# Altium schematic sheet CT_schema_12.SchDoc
size 742 x 542 mm
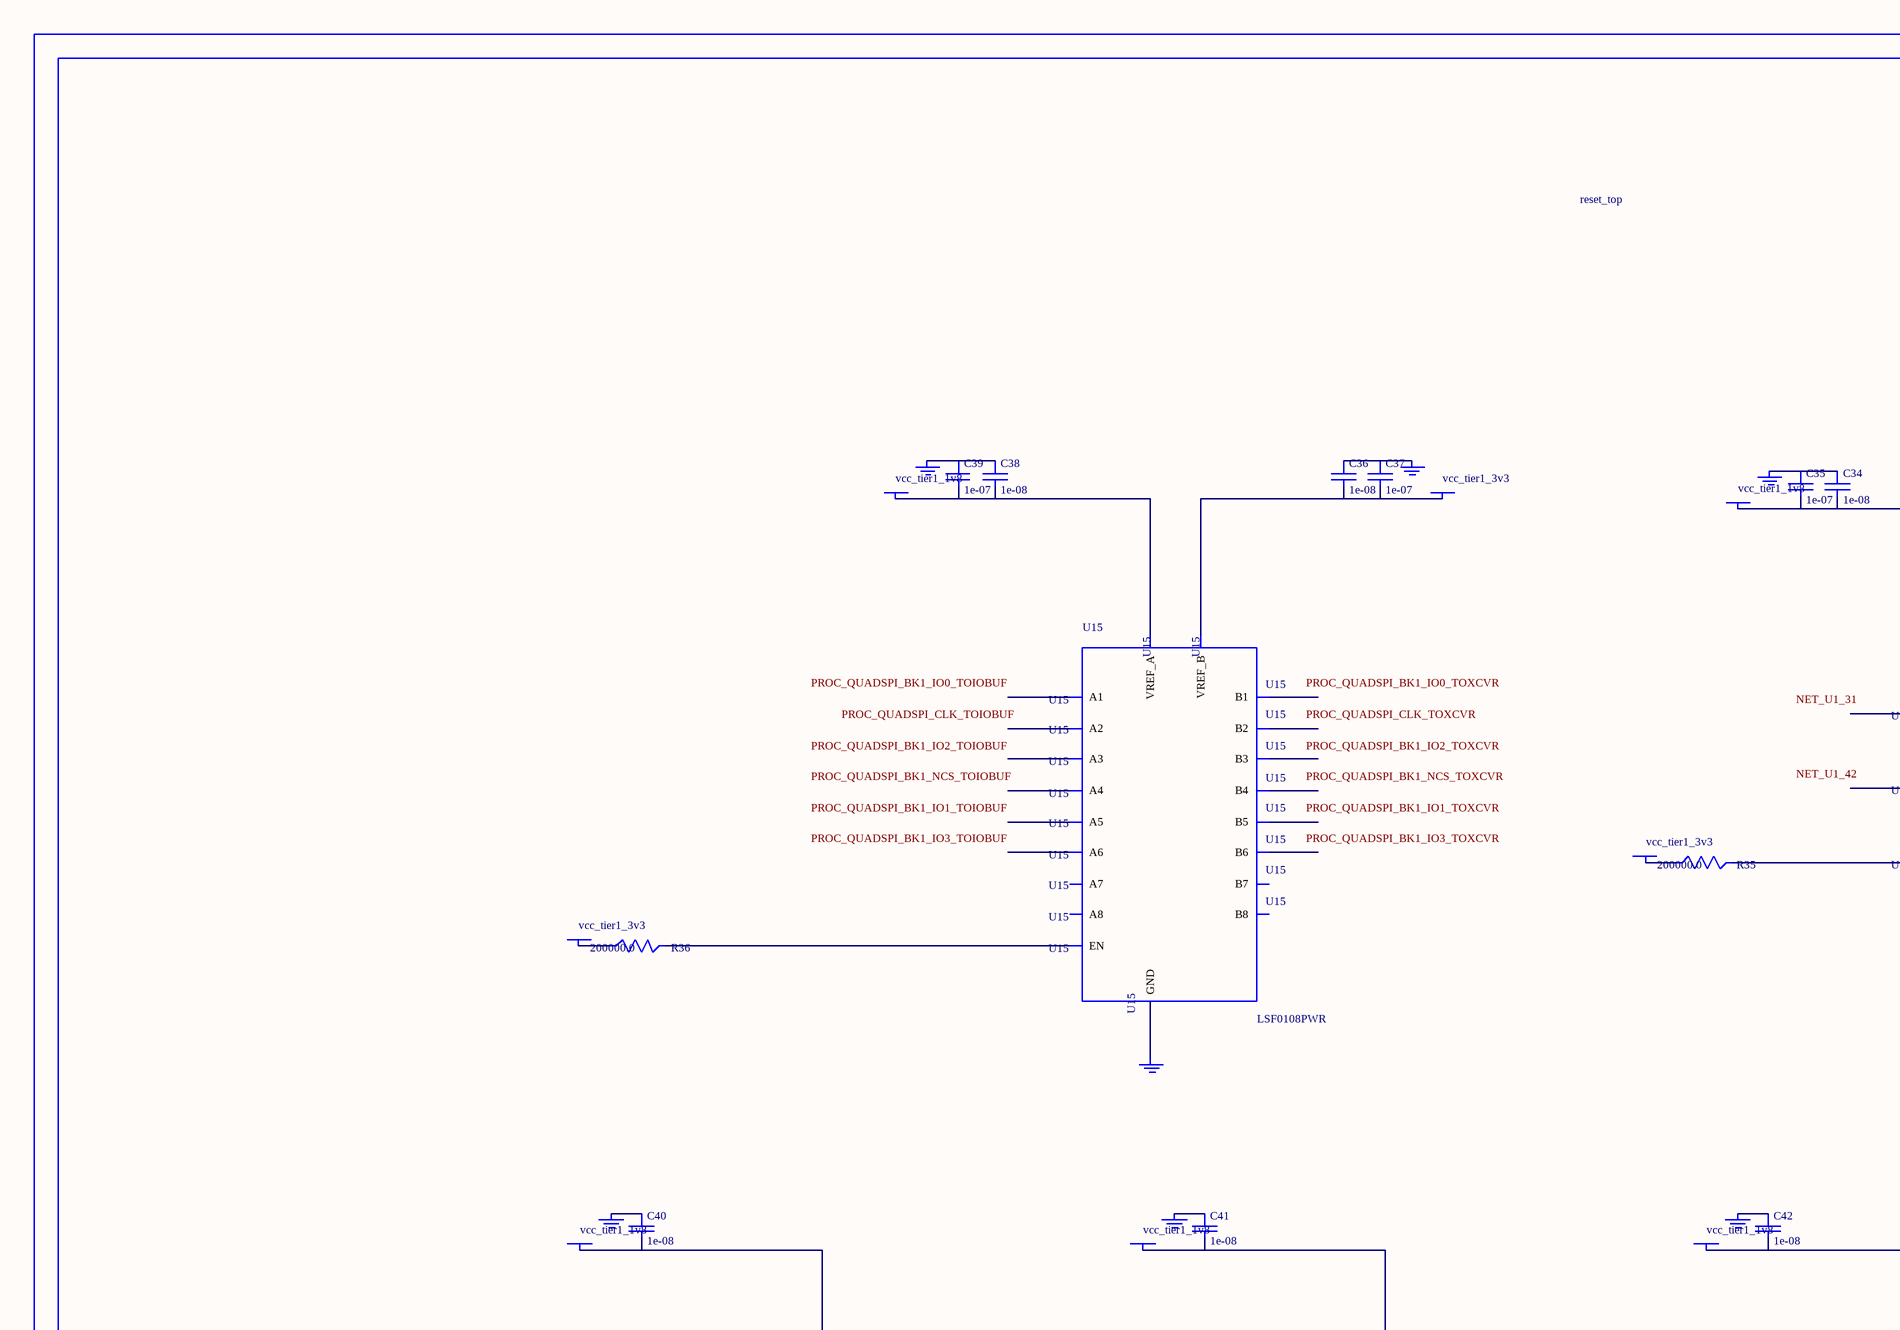
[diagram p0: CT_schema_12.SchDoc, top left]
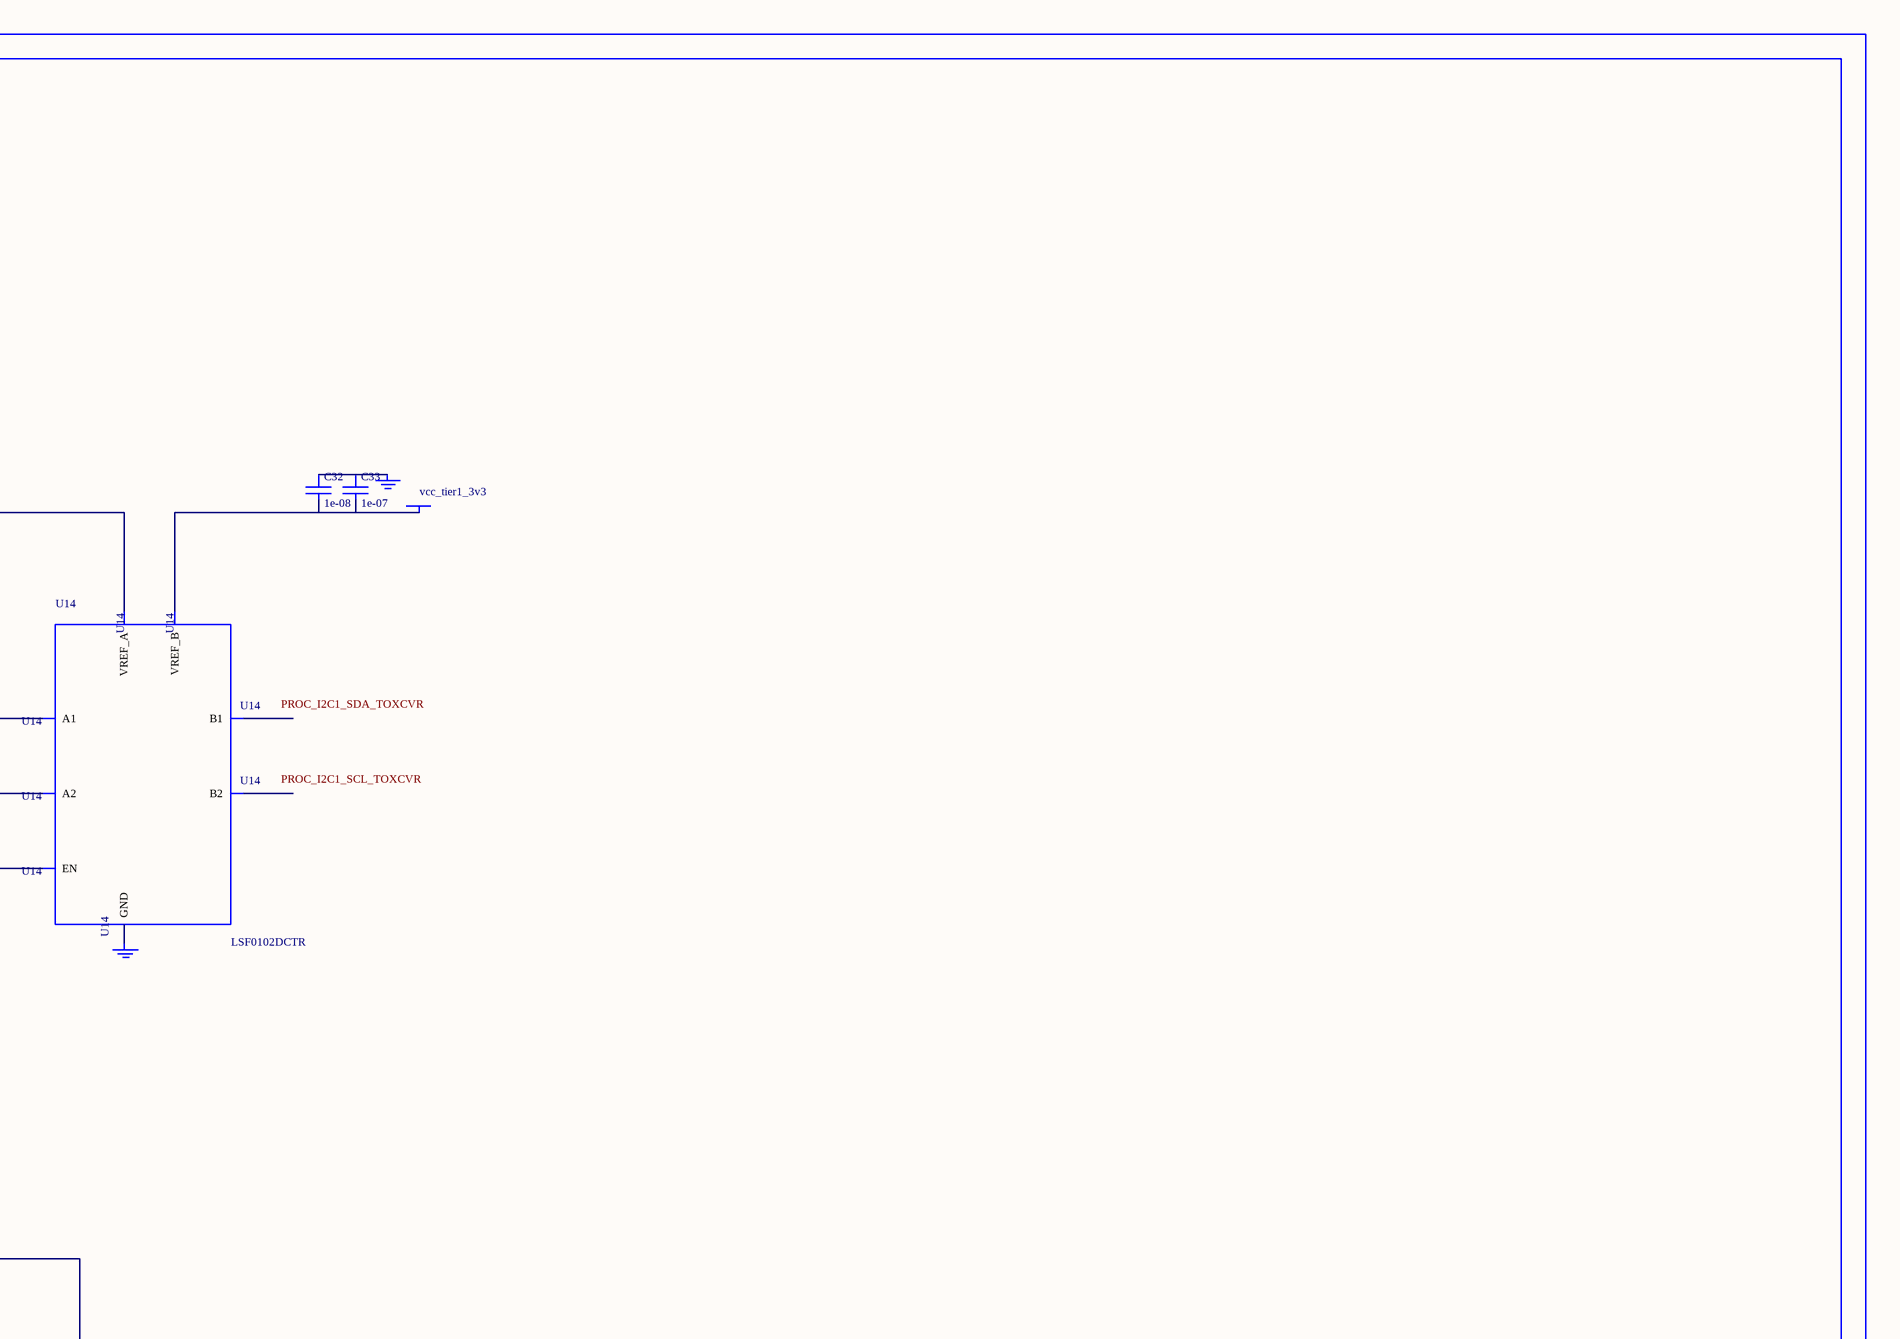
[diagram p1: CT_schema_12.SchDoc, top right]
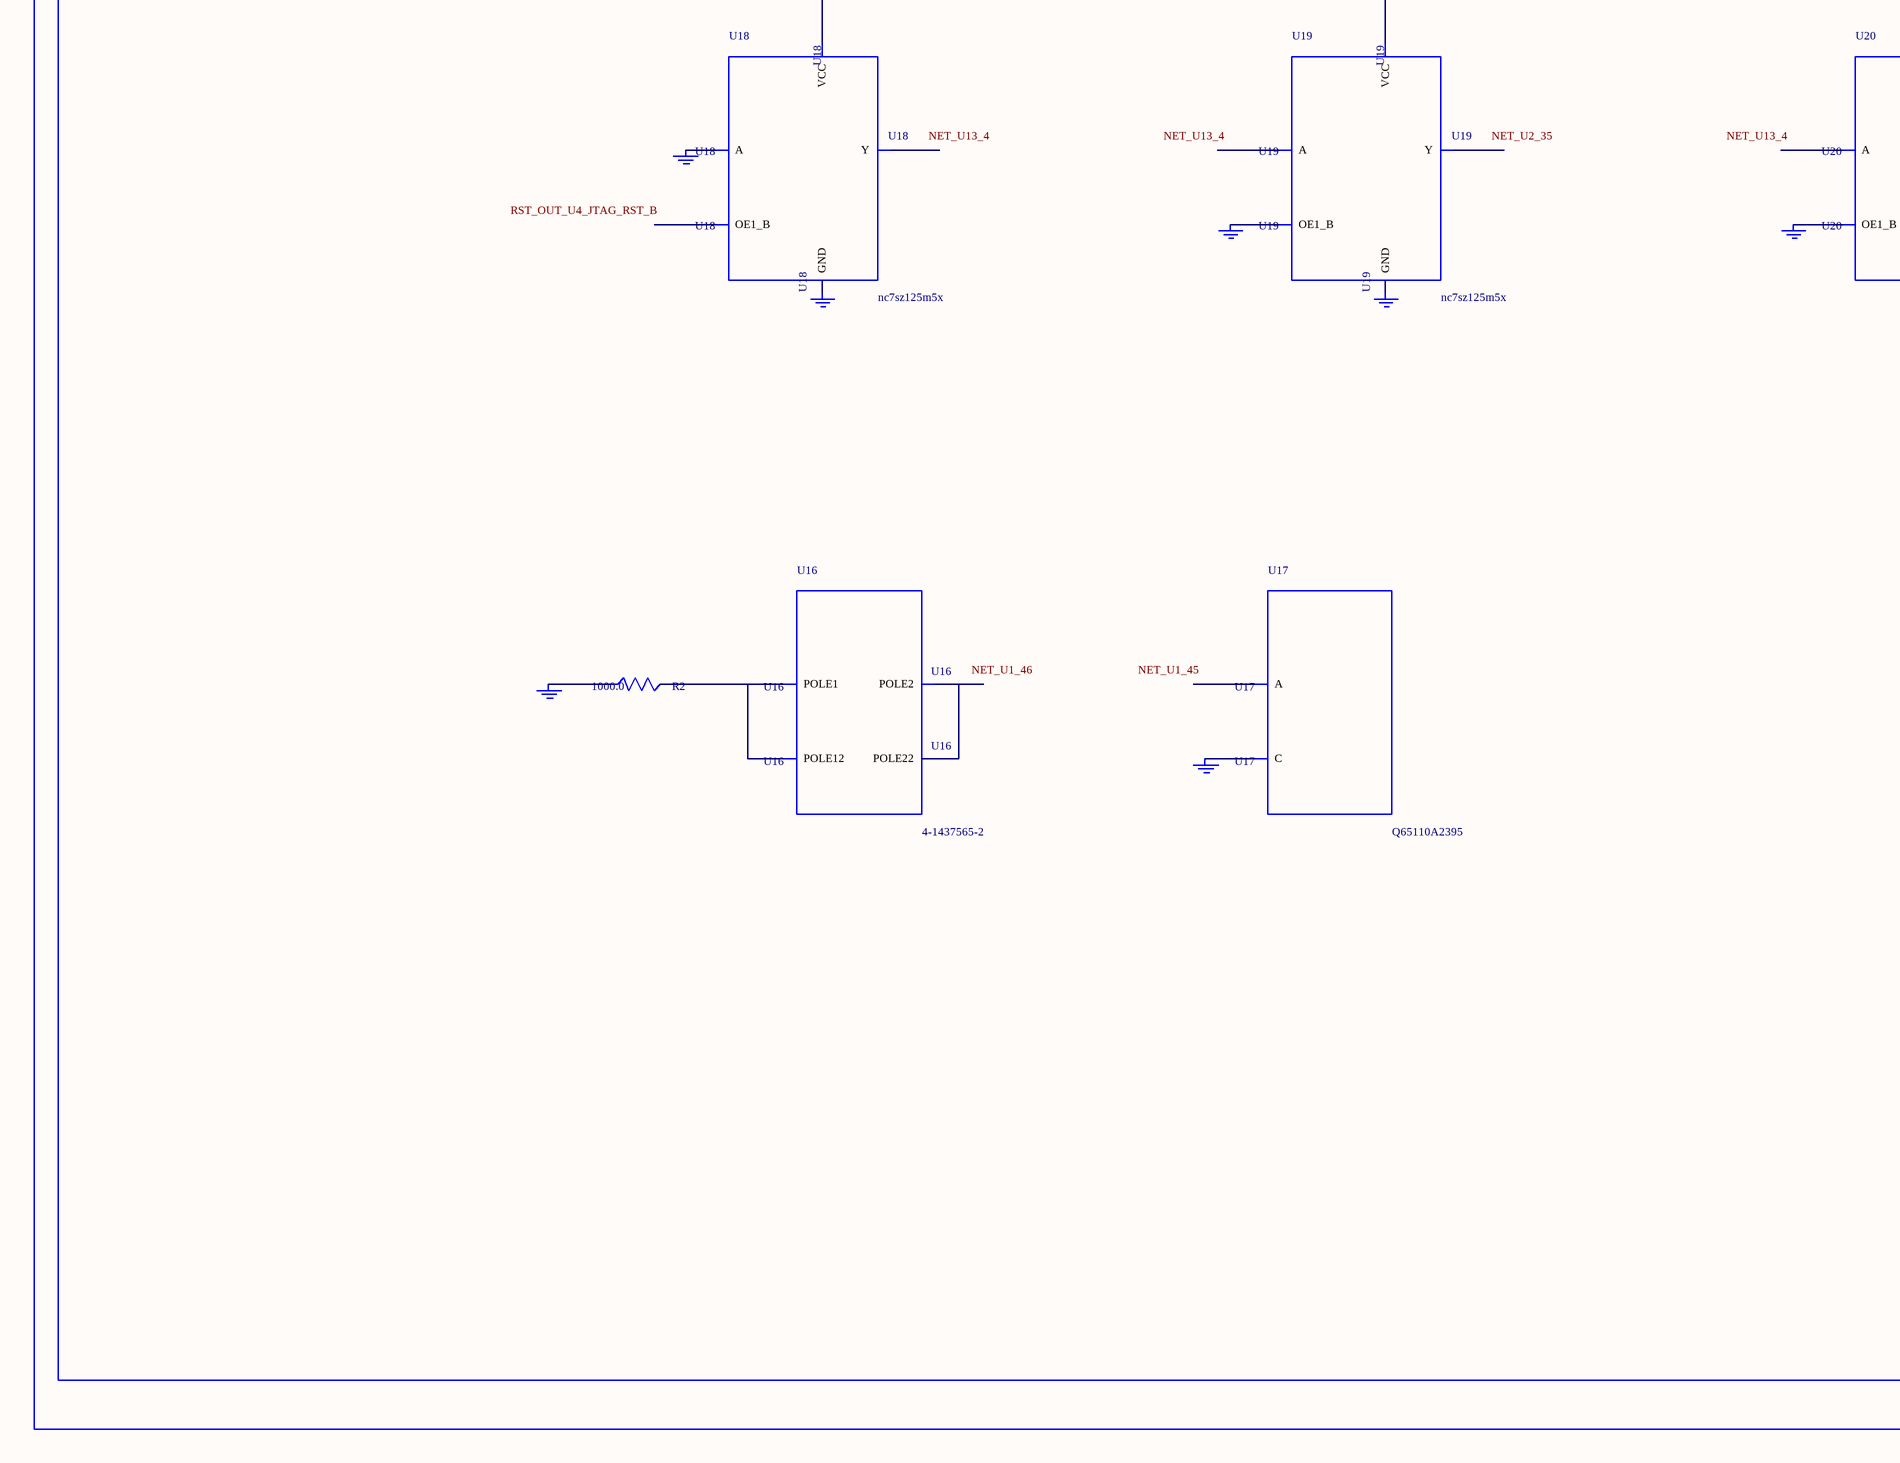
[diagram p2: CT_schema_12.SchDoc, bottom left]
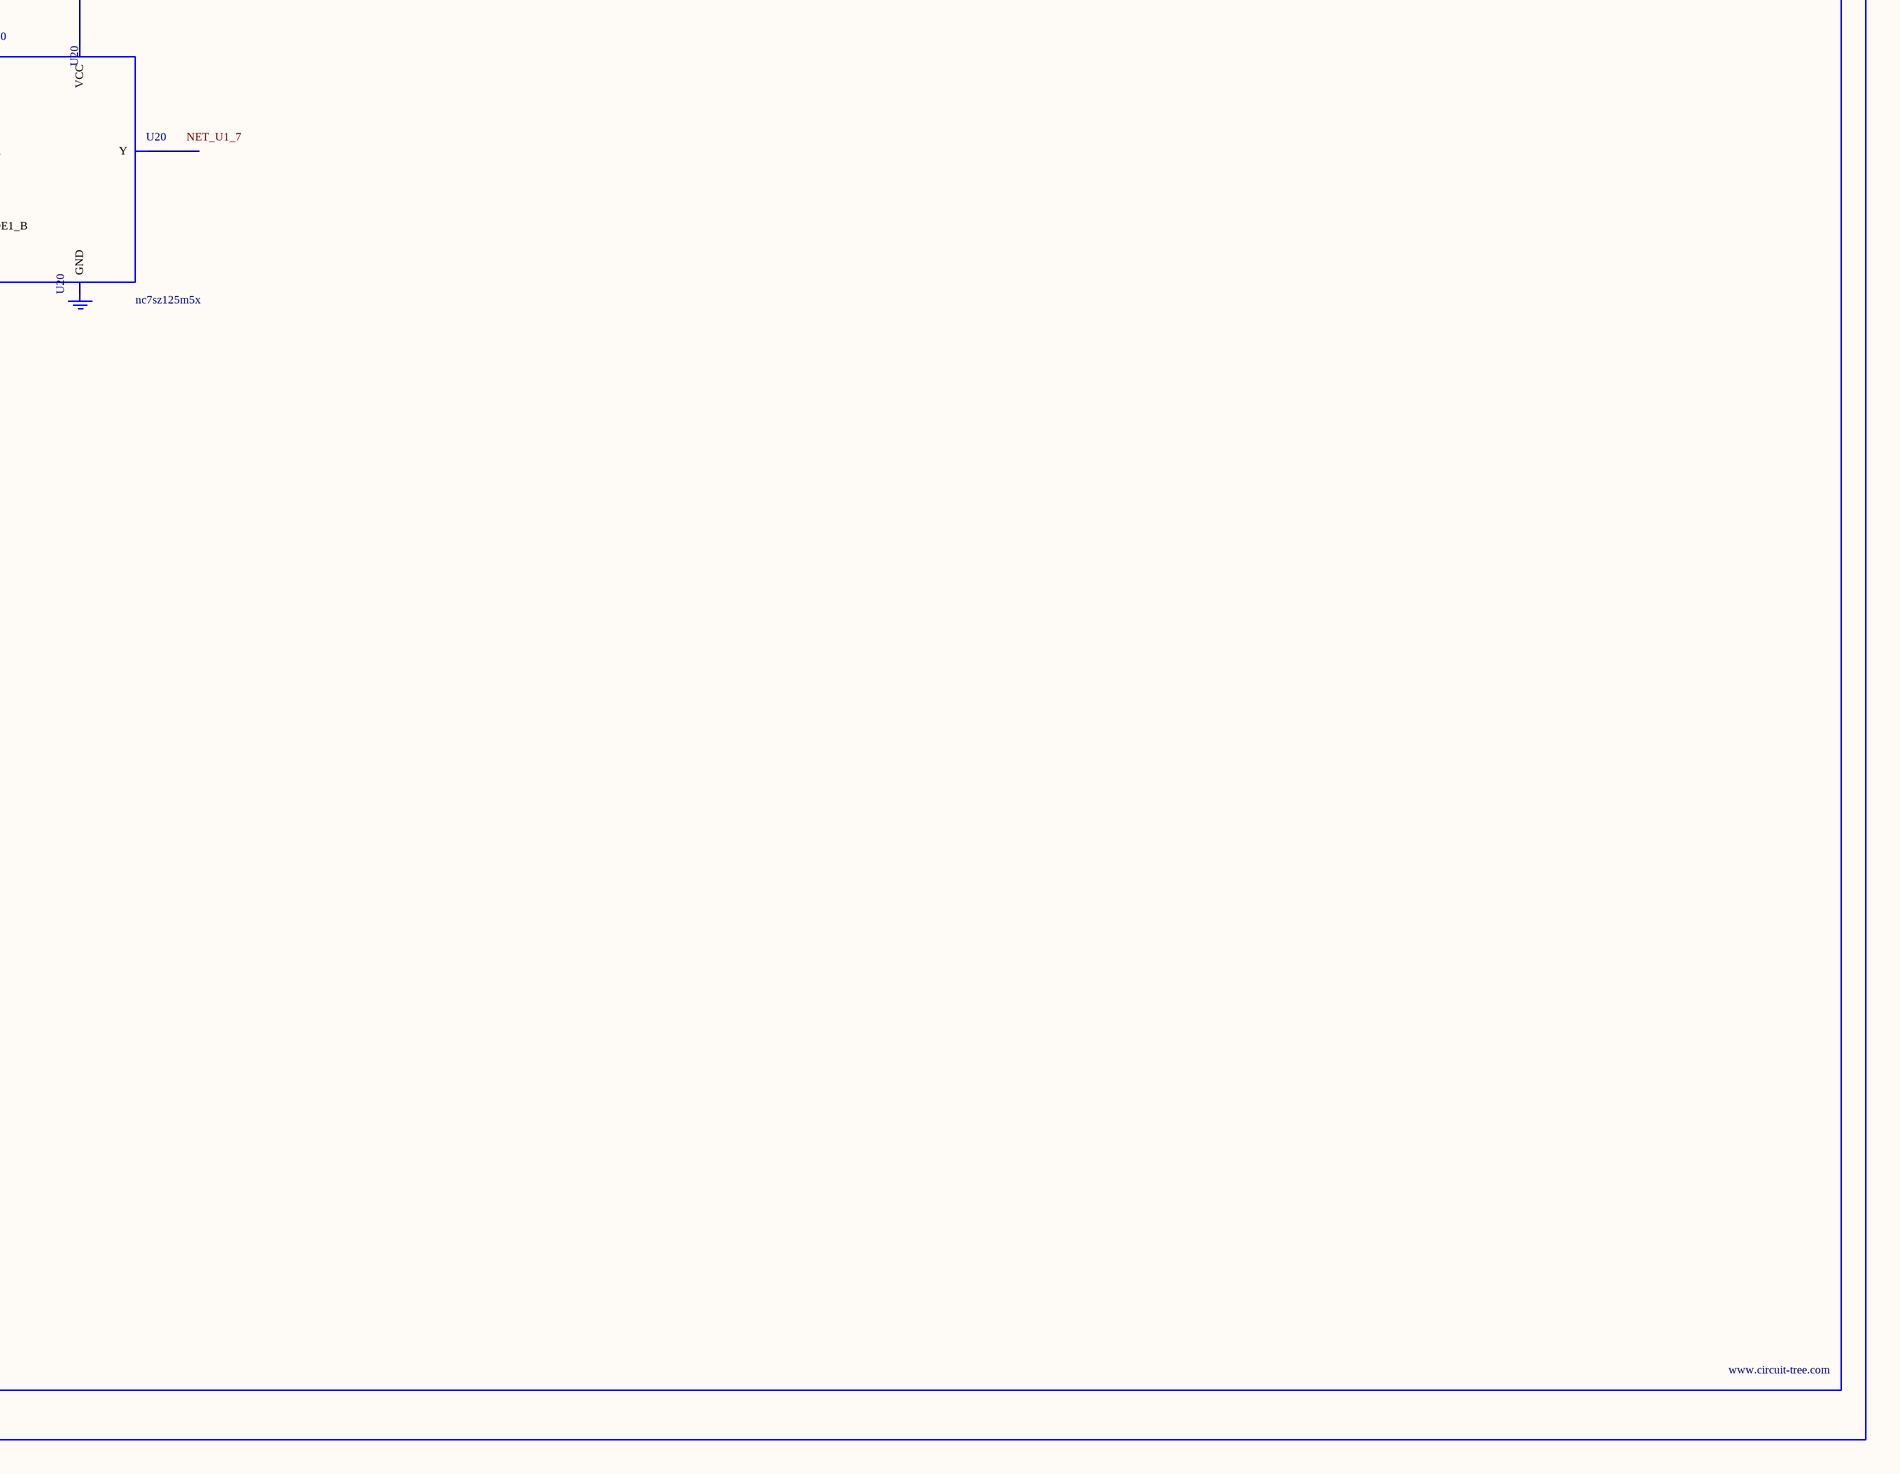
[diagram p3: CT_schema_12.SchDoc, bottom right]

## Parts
BORDER11  (no value)
C32  1e-08  [C0402]
C33  1e-07  [C0402]
C34  1e-08  [C0402]
C35  1e-07  [C0402]
C36  1e-08  [C0402]
C37  1e-07  [C0402]
C38  1e-08  [C0402]
C39  1e-07  [C0402]
C40  1e-08  [C0402]
C41  1e-08  [C0402]
C42  1e-08  [C0402]
GND_INSTANCE_11_0  (no value)
GND_INSTANCE_11_1  (no value)
GND_INSTANCE_11_2  (no value)
GND_INSTANCE_11_3  (no value)
GND_INSTANCE_11_4  (no value)
GND_INSTANCE_11_5  (no value)
GND_INSTANCE_11_6  (no value)
GND_INSTANCE_11_7  (no value)
GND_INSTANCE_11_8  (no value)
GND_INSTANCE_11_9  (no value)
GND_INSTANCE_11_10  (no value)
GND_INSTANCE_11_11  (no value)
GND_INSTANCE_11_12  (no value)
GND_INSTANCE_11_13  (no value)
GND_INSTANCE_11_14  (no value)
GND_INSTANCE_11_15  (no value)
GND_INSTANCE_11_16  (no value)
POWER_INSTANCE_11_0  vcc_tier1_1v8
POWER_INSTANCE_11_1  vcc_tier1_3v3
POWER_INSTANCE_11_2  vcc_tier1_3v3
POWER_INSTANCE_11_3  vcc_tier1_1v8
POWER_INSTANCE_11_4  vcc_tier1_3v3
POWER_INSTANCE_11_5  vcc_tier1_3v3
POWER_INSTANCE_11_6  vcc_tier1_1v8
POWER_INSTANCE_11_7  vcc_tier1_1v8
POWER_INSTANCE_11_8  vcc_tier1_1v8
R2  1000.0  [R0603]
R35  200000.0  [R0603]
R36  200000.0  [R0603]
U14  LSF0102DCTR  [DCU0008A_N]
U15  LSF0108PWR  [PW0020A]
U16  4-1437565-2  [SW_4-1437565-2]
U17  Q65110A2395  [LGM67K-G1J2-24-Z]
U18  nc7sz125m5x  [NC7SZ125M5X]
U19  nc7sz125m5x  [NC7SZ125M5X]
U20  nc7sz125m5x  [NC7SZ125M5X]

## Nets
NetC32_1: C32.1 C33.1 GND_INSTANCE_11_1.0(GND)
NetC32_2: C32.2 C33.2 POWER_INSTANCE_11_1.0(PWR) U14.7(VREF_B)
NetC34_1: C34.1 C35.1 GND_INSTANCE_11_0.0(GND)
NetC34_2: C34.2 C35.2 POWER_INSTANCE_11_0.0(PWR) U14.2(VREF_A)
NetC36_1: C36.1 C37.1 GND_INSTANCE_11_4.0(GND)
NetC36_2: C36.2 C37.2 POWER_INSTANCE_11_4.0(PWR) U15.19(VREF_B)
NetC38_1: C38.1 C39.1 GND_INSTANCE_11_3.0(GND)
NetC38_2: C38.2 C39.2 POWER_INSTANCE_11_3.0(PWR) U15.2(VREF_A)
NetC40_1: C40.1 GND_INSTANCE_11_8.0(GND)
NetC40_2: C40.2 POWER_INSTANCE_11_6.0(PWR) U18.5(VCC)
NetC41_1: C41.1 GND_INSTANCE_11_11.0(GND)
NetC41_2: C41.2 POWER_INSTANCE_11_7.0(PWR) U19.5(VCC)
NetC42_1: C42.1 GND_INSTANCE_11_14.0(GND)
NetC42_2: C42.2 POWER_INSTANCE_11_8.0(PWR) U20.5(VCC)
NetGND_INSTANCE_11_2_0: GND_INSTANCE_11_2.0(GND) U14.1(GND)
NetGND_INSTANCE_11_5_0: GND_INSTANCE_11_5.0(GND) U15.1(GND)
NetGND_INSTANCE_11_6_0: GND_INSTANCE_11_6.0(GND) R2.1
NetGND_INSTANCE_11_7_0: GND_INSTANCE_11_7.0(GND) U17.C
NetGND_INSTANCE_11_9_0: GND_INSTANCE_11_9.0(GND) U18.2(A)
NetGND_INSTANCE_11_10_0: GND_INSTANCE_11_10.0(GND) U18.3(GND)
NetGND_INSTANCE_11_12_0: GND_INSTANCE_11_12.0(GND) U19.1(OE1_B)
NetGND_INSTANCE_11_13_0: GND_INSTANCE_11_13.0(GND) U19.3(GND)
NetGND_INSTANCE_11_15_0: GND_INSTANCE_11_15.0(GND) U20.1(OE1_B)
NetGND_INSTANCE_11_16_0: GND_INSTANCE_11_16.0(GND) U20.3(GND)
NetPOWER_INSTANCE_11_2_0: POWER_INSTANCE_11_2.0(PWR) R35.1
NetPOWER_INSTANCE_11_5_0: POWER_INSTANCE_11_5.0(PWR) R36.1
NetR2_2: R2.2 U16.1(POLE1) U16.2(POLE12)
NetR35_2: R35.2 U14.8(EN)
NetR36_2: R36.2 U15.20(EN)
NetU16_3: U16.3(POLE2) U16.4(POLE22)

Not connected (* = marked no-connect by the designer): U14 3(A1) 4(A2) 5(B2) 6(B1); U15 3(A1) 4(A2) 5(A3) 6(A4) 7(A5) 8(A6) 9(A7) 10(A8) 11(B8) 12(B7) 13(B6) 14(B5) 15(B4) 16(B3) 17(B2) 18(B1); U17 A; U18 1(OE1_B) 4(Y); U19 2(A) 4(Y); U20 2(A) 4(Y)

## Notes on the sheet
- Labels drawn without touching a wire or pin: NET_U1_7, NET_U1_31, NET_U1_42, NET_U1_45, NET_U1_46, NET_U2_35, NET_U13_4, PROC_I2C1_SCL_TOXCVR, PROC_I2C1_SDA_TOXCVR, PROC_QUADSPI_BK1_IO0_TOIOBUF, PROC_QUADSPI_BK1_IO0_TOXCVR, PROC_QUADSPI_BK1_IO1_TOIOBUF, PROC_QUADSPI_BK1_IO1_TOXCVR, PROC_QUADSPI_BK1_IO2_TOIOBUF, PROC_QUADSPI_BK1_IO2_TOXCVR, PROC_QUADSPI_BK1_IO3_TOIOBUF, PROC_QUADSPI_BK1_IO3_TOXCVR, PROC_QUADSPI_BK1_NCS_TOIOBUF, PROC_QUADSPI_BK1_NCS_TOXCVR, PROC_QUADSPI_CLK_TOIOBUF, PROC_QUADSPI_CLK_TOXCVR, RST_OUT_U4_JTAG_RST_B

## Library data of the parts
BORDER11 = BORDER_PAGE11
C32 C34 C36 C38 C40-C42 = C0402C103K3RAC
C33 C35 C37 C39 = C0402C104K3RACTU
GND_INSTANCE_11_0-GND_INSTANCE_11_16 = GND
POWER_INSTANCE_11_0-POWER_INSTANCE_11_8 = PWR
R2 = RC0603JR-071KL
R35 R36 = RC0603JR-07200KL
